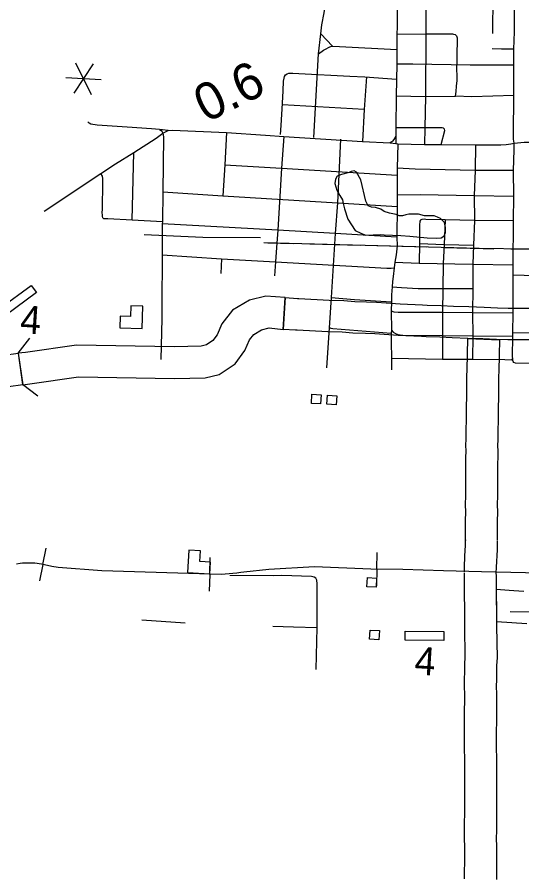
# Model space of a CAD drawing. Extents: x 1366406 to 1373462, y 376856 to 381998.
# Drawn here: x 1369209.2 to 1369273.7, y 379865.5 to 379974.8 of the extents above; entities that cross this region are included whole.
import ezdxf

# ---------------------------------------------------------------- set-up
doc = ezdxf.new("R2010")
doc.units = 0
for name, color, linetype in [('10', 7, 'Continuous'), ('15', 7, 'Continuous'), ('33', 7, 'Continuous'), ('34', 7, 'Continuous'), ('35', 7, 'Continuous'), ('37', 7, 'Continuous'), ('40', 7, 'Continuous'), ('43', 7, 'Continuous'), ('48', 7, 'Continuous'), ('56', 7, 'Continuous'), ('58', 7, 'Continuous')]:
    doc.layers.add(name, color=color, linetype=linetype)

msp = doc.modelspace()

# ---------------------------------------------------------------- linework, layer by layer
at = {"layer": '10'}
msp.add_line((1369266.5, 379908.05), (1369266.5, 379907.96), dxfattribs=at)
for points in [[(1369243.2, 379934.94), (1369243.45, 379938.99), (1369241.02, 379939.19), (1369238.93, 379938.67), (1369236.73, 379937.4), (1369235.4, 379935.65), (1369234.79, 379934.25), (1369234.25, 379933.5), (1369233.42, 379932.96), (1369232.72, 379932.79), (1369229.33, 379932.72), (1369216.84, 379932.9), (1369210.29, 379931.99), (1369209.39, 379931.88), (1369209.95, 379927.86)], [(1369243.2, 379934.94), (1369243.45, 379938.99), (1369245.03, 379938.89), (1369245.21, 379938.88), (1369249.1, 379938.68), (1369250.98, 379938.61), (1369252.35, 379938.5), (1369253.86, 379938.46), (1369255.11, 379938.4), (1369256.35, 379938.34), (1369258.16, 379938.21), (1369261.02, 379938.06), (1369261.59, 379938.05), (1369263.38, 379937.98), (1369264.95, 379937.91), (1369266.93, 379937.84), (1369268.87, 379937.76)], [(1369268.87, 379937.76), (1369270.58, 379937.7), (1369271.96, 379937.66), (1369274.8, 379937.64)], [(1369209.95, 379927.86), (1369210.85, 379927.98), (1369217.09, 379928.85), (1369229.34, 379928.67), (1369233.24, 379928.75), (1369235.06, 379929.19), (1369237.09, 379930.53), (1369238.33, 379932.23), (1369238.92, 379933.59), (1369239.46, 379934.3), (1369240.46, 379934.88), (1369241.42, 379935.12), (1369243.2, 379934.94)], [(1369268.71, 379933.72), (1369266.79, 379933.79), (1369264.79, 379933.86), (1369263.22, 379933.94), (1369261.47, 379934), (1369260.87, 379934.01), (1369257.91, 379934.17), (1369256.1, 379934.3), (1369254.92, 379934.36), (1369253.71, 379934.41), (1369252.12, 379934.46), (1369250.74, 379934.57), (1369248.93, 379934.63), (1369244.98, 379934.83), (1369244.78, 379934.84), (1369243.2, 379934.94)], [(1369266.5, 379907.96), (1369266.48, 379908.65), (1369266.49, 379909.32), (1369266.48, 379910), (1369266.51, 379910.73), (1369266.52, 379911.38), (1369266.51, 379912.78), (1369266.52, 379913.47), (1369266.52, 379914.19), (1369266.53, 379914.9), (1369266.52, 379915.65), (1369266.54, 379916.38), (1369266.53, 379917.14), (1369266.55, 379917.91), (1369266.56, 379918.56), (1369266.57, 379919.36), (1369266.55, 379920.12), (1369266.58, 379920.91), (1369266.61, 379924.57), (1369266.63, 379925.32), (1369266.65, 379926.04), (1369266.67, 379926.74), (1369266.66, 379928.95), (1369266.69, 379929.77), (1369266.75, 379931.75), (1369266.81, 379933.77), (1369270.85, 379933.62)], [(1369274.79, 379933.59), (1369271.89, 379933.61), (1369270.45, 379933.65), (1369268.71, 379933.72)], [(1369270.85, 379933.62), (1369270.8, 379931.63), (1369270.74, 379929.62), (1369270.71, 379928.88), (1369270.72, 379926.69), (1369270.7, 379925.93), (1369270.68, 379925.21), (1369270.66, 379924.5), (1369270.63, 379920.81), (1369270.6, 379920.09), (1369270.62, 379919.38), (1369270.61, 379918.5), (1369270.6, 379917.85), (1369270.58, 379917.11), (1369270.59, 379916.36), (1369270.57, 379915.62), (1369270.58, 379914.9), (1369270.57, 379914.16), (1369270.57, 379913.44), (1369270.56, 379912.77), (1369270.57, 379911.35), (1369270.56, 379910.62), (1369270.53, 379909.96), (1369270.54, 379909.33), (1369270.53, 379908.66), (1369270.55, 379908.05)], [(1369209.39, 379931.87), (1369198.35, 379930.34), (1369198.13, 379930.31)], [(1369209.39, 379931.88), (1369209.94, 379927.87)], [(1369209.95, 379927.86), (1369198.93, 379926.33), (1369198.71, 379926.3)], [(1369266.35, 379903.96), (1369266.38, 379904.71), (1369266.47, 379906.86), (1369266.48, 379907.16), (1369266.5, 379908.05)], [(1369270.55, 379907.96), (1369270.53, 379907.09), (1369270.52, 379906.75), (1369270.43, 379904.53), (1369270.39, 379903.76)], [(1369266.39, 379864.71), (1369266.39, 379865.72), (1369266.41, 379866.76), (1369266.4, 379867.81), (1369266.42, 379868.83), (1369266.38, 379869.82), (1369266.39, 379870.9), (1369266.39, 379871.94), (1369266.4, 379872.98), (1369266.41, 379874.02), (1369266.4, 379875.04), (1369266.4, 379876.08), (1369266.4, 379877.12), (1369266.4, 379878.16), (1369266.41, 379879.19), (1369266.4, 379880.19), (1369266.38, 379881.22), (1369266.37, 379882.14), (1369266.38, 379883.31), (1369266.39, 379885.08), (1369266.39, 379885.34), (1369266.39, 379886.35), (1369266.4, 379887.34), (1369266.4, 379888.31), (1369266.37, 379889.27), (1369266.39, 379890.25), (1369266.4, 379891.18), (1369266.42, 379892.15), (1369266.47, 379893.05), (1369266.42, 379896.96), (1369266.35, 379903.29), (1369266.35, 379903.83)], [(1369270.39, 379903.89), (1369270.4, 379903.34), (1369270.47, 379897.01), (1369270.52, 379892.97), (1369270.47, 379892), (1369270.45, 379891.13), (1369270.44, 379890.19), (1369270.42, 379889.28), (1369270.45, 379888.36), (1369270.45, 379887.33), (1369270.44, 379886.33), (1369270.44, 379885.32), (1369270.44, 379885.06), (1369270.43, 379883.29), (1369270.42, 379882.15), (1369270.43, 379881.27), (1369270.45, 379880.25), (1369270.46, 379879.19), (1369270.45, 379878.15), (1369270.45, 379877.12), (1369270.45, 379876.09), (1369270.45, 379875.05), (1369270.46, 379874), (1369270.45, 379872.96), (1369270.44, 379871.92), (1369270.44, 379870.88), (1369270.43, 379869.89), (1369270.47, 379868.87), (1369270.45, 379867.77), (1369270.46, 379866.74), (1369270.44, 379865.7), (1369270.44, 379864.65)], [(1369273.96, 379901.43), (1369273.31, 379901.48), (1369272.69, 379901.52), (1369272.08, 379901.56), (1369270.42, 379901.69), (1369270.47, 379897.6)], [(1369270.47, 379897.6), (1369272.42, 379897.48), (1369273.03, 379897.44), (1369273.68, 379897.39), (1369274.35, 379897.35)]]:
    msp.add_lwpolyline(points, dxfattribs=at)
at = {"layer": '15'}
msp.add_lwpolyline([(1369243.45, 379938.99), (1369243.2, 379934.94)], dxfattribs=at)
at = {"layer": '33'}
for points in [[(1369247.12, 379959.46), (1369247.73, 379970.16), (1369248.03, 379972.72), (1369248.16, 379973.86), (1369248.46, 379975.38), (1369248.71, 379977.22), (1369248.87, 379978.16), (1369249.08, 379980.55)], [(1369257.87, 379980.81), (1369257.76, 379976.94), (1369257.75, 379976.81), (1369257.76, 379973.6), (1369257.74, 379972.68), (1369257.74, 379970.7), (1369257.71, 379968.83), (1369257.65, 379964.78), (1369257.6, 379960.68), (1369257.6, 379959.64), (1369257.61, 379958.68)], [(1369261.45, 379979.35), (1369261.45, 379973.54), (1369261.41, 379972.71), (1369261.37, 379964.71), (1369261.32, 379960.7), (1369261.24, 379958.58)], [(1369269.97, 379972.76), (1369269.99, 379973.45), (1369270.01, 379976.84), (1369270.03, 379979.21)], [(1369257.06, 379931.24), (1369263.54, 379931.14), (1369267.4, 379931.12), (1369271.51, 379931.08), (1369272.36, 379931.06), (1369272.46, 379931.1), (1369272.53, 379931.2), (1369272.52, 379931.42), (1369272.56, 379934.05), (1369272.56, 379934.48), (1369272.58, 379937.07), (1369272.58, 379941.9), (1369272.59, 379943.2), (1369272.64, 379948.8), (1369272.69, 379951.96), (1369272.64, 379955.22), (1369272.71, 379957.87), (1369272.7, 379958.73), (1369272.64, 379959.23), (1369272.62, 379959.92), (1369272.67, 379964.74), (1369272.67, 379968.71), (1369272.66, 379970.76), (1369272.74, 379972.95), (1369272.76, 379973.47), (1369272.74, 379975.81)], [(1369248.03, 379972.72), (1369249.52, 379971.14), (1369249.52, 379971.14)], [(1369257.74, 379972.68), (1369261.41, 379972.71), (1369262.35, 379972.71), (1369264.82, 379972.7), (1369264.98, 379972.66), (1369265.18, 379972.6), (1369265.34, 379972.43), (1369265.45, 379972.19), (1369265.42, 379971.82), (1369265.37, 379970.16), (1369265.41, 379968.78)], [(1369247.73, 379970.16), (1369248.38, 379970.6), (1369248.69, 379970.79), (1369249, 379970.96), (1369249.16, 379971.04), (1369249.31, 379971.1), (1369249.52, 379971.14), (1369250.4, 379971.08), (1369257.74, 379970.7)], [(1369272.66, 379970.76), (1369271.58, 379970.74), (1369271.08, 379970.76), (1369269.9, 379970.79)], [(1369272.67, 379968.71), (1369269.96, 379968.72), (1369267.11, 379968.72), (1369259.79, 379968.82), (1369257.71, 379968.83)], [(1369258.45, 379968.85), (1369258.45, 379968.85)], [(1369265.23, 379964.76), (1369265.3, 379965.33), (1369265.36, 379966.01), (1369265.42, 379966.76), (1369265.41, 379968.78)], [(1369242.89, 379959.84), (1369242.97, 379960.97), (1369243.13, 379963.86), (1369243.21, 379965.43), (1369243.27, 379966.64), (1369243.34, 379967.02), (1369243.38, 379967.24), (1369243.52, 379967.45), (1369243.73, 379967.6), (1369243.92, 379967.68), (1369244.44, 379967.7), (1369245.22, 379967.65), (1369251.73, 379967.29), (1369253.65, 379967.2), (1369257.68, 379966.92)], [(1369253.84, 379967.19), (1369253.57, 379963.04), (1369253.36, 379958.96)], [(1369257.65, 379964.78), (1369261.37, 379964.71), (1369265.23, 379964.76)], [(1369272.67, 379964.81), (1369267.3, 379964.66), (1369265.23, 379964.76)], [(1369253.57, 379963.04), (1369243.12, 379963.65)], [(1369228.52, 379960.37), (1369227.41, 379960.5), (1369226.4, 379960.58), (1369223.31, 379960.78), (1369219.46, 379961.04), (1369218.67, 379961.16), (1369218.44, 379961.29), (1369218.27, 379961.44)], [(1369212.71, 379950.03), (1369219.92, 379954.84), (1369221.82, 379956.09), (1369224.13, 379957.56), (1369227, 379959.36), (1369227.86, 379960), (1369228.1, 379960.16), (1369228.52, 379960.37), (1369229.08, 379960.41), (1369235.99, 379960.09), (1369240.95, 379959.75), (1369243.29, 379959.59), (1369253.36, 379958.96), (1369256.88, 379958.77), (1369257.61, 379958.68), (1369257.85, 379958.64)], [(1369227.41, 379960.5), (1369227.63, 379960.34), (1369227.75, 379960.18), (1369227.86, 379960)], [(1369263.37, 379958.57), (1369263.85, 379960.36), (1369263.8, 379960.54), (1369263.67, 379960.64), (1369263.51, 379960.7), (1369261.32, 379960.7), (1369257.6, 379960.68)], [(1369227.86, 379960), (1369227.92, 379959.55), (1369227.85, 379952.5), (1369227.79, 379948.68), (1369227.78, 379948.44), (1369227.74, 379944.47), (1369227.71, 379937.9), (1369227.72, 379936.33), (1369227.58, 379931.1)], [(1369235.99, 379960.09), (1369235.76, 379955.98), (1369235.52, 379952.02)], [(1369243.29, 379959.59), (1369243, 379955.55), (1369242.53, 379947.62), (1369242.34, 379945.4), (1369242.24, 379943.55)], [(1369250.55, 379959.24), (1369250.13, 379951.11), (1369249.85, 379947.17), (1369249.35, 379938.99), (1369249.1, 379935.13), (1369248.73, 379930.02)], [(1369257.6, 379959.64), (1369257.49, 379959.42), (1369257.36, 379959.22), (1369257.18, 379959), (1369257.07, 379958.9), (1369256.88, 379958.77)], [(1369257.85, 379958.64), (1369257.76, 379955.52), (1369257.75, 379954.63), (1369257.77, 379952.15), (1369257.78, 379950.65), (1369257.73, 379946.7), (1369257.76, 379945.6), (1369257.64, 379944.46), (1369257.47, 379943.52), (1369257.37, 379942.79), (1369257.24, 379941.71), (1369257.19, 379941.06), (1369257.12, 379940.38), (1369257.05, 379939.34), (1369257.04, 379939.21), (1369257.05, 379938.47), (1369257.02, 379937.3), (1369257.04, 379934.84), (1369257.01, 379934.47), (1369257.02, 379933.31), (1369257.06, 379931.24), (1369257.05, 379929.75)], [(1369257.85, 379958.64), (1369261.24, 379958.58), (1369263.37, 379958.57), (1369267.79, 379958.5), (1369271.03, 379958.51), (1369271.71, 379958.55), (1369272.27, 379958.64), (1369272.7, 379958.73)], [(1369267.79, 379958.5), (1369267.72, 379955.26), (1369267.62, 379952.05), (1369267.63, 379948.87), (1369267.51, 379945.7), (1369267.45, 379943.29), (1369267.43, 379940.14), (1369267.41, 379937.08), (1369267.44, 379934.1), (1369267.4, 379931.12)], [(1369272.7, 379958.73), (1369273.15, 379958.76), (1369273.97, 379958.85), (1369274.62, 379958.86), (1369275.99, 379958.92), (1369277.82, 379958.93), (1369287.45, 379958.94)], [(1369223.95, 379948.88), (1369224.13, 379957.56)], [(1369235.76, 379955.98), (1369243, 379955.55), (1369257.75, 379954.63)], [(1369272.64, 379955.22), (1369267.72, 379955.26), (1369260.07, 379955.42), (1369257.76, 379955.52)], [(1369227.79, 379948.68), (1369223.95, 379948.88), (1369220.84, 379949.05), (1369220.33, 379949.08), (1369220.2, 379949.21), (1369220.15, 379949.34), (1369220.12, 379949.49), (1369220.11, 379949.93), (1369220.12, 379950.21), (1369220.18, 379953.78), (1369220.18, 379954.21), (1369220.13, 379954.53), (1369219.92, 379954.84)], [(1369227.85, 379952.5), (1369235.52, 379952.02), (1369250.13, 379951.11), (1369257.78, 379950.65)], [(1369257.77, 379952.15), (1369260.72, 379952.19), (1369267.62, 379952.05), (1369272.69, 379951.96)], [(1369257.73, 379946.7), (1369249.85, 379947.17), (1369242.53, 379947.62), (1369227.78, 379948.44)], [(1369272.64, 379948.8), (1369267.63, 379948.87), (1369263.9, 379948.94), (1369261.42, 379948.99), (1369261.22, 379949), (1369260.91, 379948.98), (1369260.81, 379948.95), (1369260.74, 379948.89), (1369260.67, 379948.77), (1369260.62, 379948.25), (1369260.61, 379945.9), (1369260.58, 379943.41)], [(1369263.9, 379948.94), (1369263.76, 379945.8), (1369263.63, 379943.37), (1369263.63, 379943.37), (1369263.62, 379940.18), (1369263.57, 379937.12), (1369263.54, 379934.16), (1369263.54, 379931.14)], [(1369260.61, 379945.9), (1369263.76, 379945.8), (1369267.51, 379945.7)], [(1369227.74, 379944.47), (1369235.34, 379943.93), (1369242.24, 379943.55), (1369256.46, 379942.75), (1369257, 379942.77), (1369257.37, 379942.79)], [(1369235.34, 379943.93), (1369235.24, 379942.09)], [(1369242.24, 379943.55), (1369242.11, 379941.76)], [(1369257.47, 379943.52), (1369260.58, 379943.41), (1369267.45, 379943.29), (1369272.59, 379943.2)], [(1369272.58, 379941.9), (1369275.39, 379941.82)], [(1369257.12, 379940.38), (1369258.31, 379940.28), (1369260.45, 379940.18), (1369262.42, 379940.18), (1369263.62, 379940.18), (1369265.51, 379940.14), (1369267.43, 379940.14)], [(1369249.35, 379938.99), (1369252.33, 379938.76), (1369257.05, 379938.47)], [(1369257.02, 379937.3), (1369257.36, 379937.19), (1369257.9, 379937.15), (1369263.57, 379937.12), (1369267.41, 379937.08), (1369272.58, 379937.07)], [(1369249.11, 379935.17), (1369249.29, 379935.1), (1369249.57, 379935.05), (1369257.01, 379934.47)], [(1369257.04, 379934.84), (1369257.25, 379934.6), (1369257.56, 379934.39), (1369257.85, 379934.27), (1369258.48, 379934.21), (1369263.54, 379934.16), (1369267.44, 379934.1), (1369272.56, 379934.05)], [(1369287.35, 379934.58), (1369281.27, 379934.48), (1369280.6, 379934.45), (1369279.34, 379934.45), (1369279.14, 379934.45), (1369276.63, 379934.45), (1369272.56, 379934.48)], [(1369276.72, 379930.57), (1369272.89, 379930.62), (1369272.69, 379930.7), (1369272.57, 379930.82), (1369272.53, 379930.96), (1369272.53, 379931.2)], [(1369272.21, 379898.87), (1369287.08, 379898.65), (1369293.15, 379898.58), (1369295.08, 379898.56), (1369301.85, 379898.47)]]:
    msp.add_lwpolyline(points, dxfattribs=at)
at = {"layer": '34'}
for points in [[(1369225.46, 379947.07), (1369232.97, 379946.72), (1369240.32, 379946.69)], [(1369247.41, 379891.48), (1369247.54, 379896.82), (1369247.57, 379901.78), (1369247.57, 379902.43), (1369247.53, 379902.88), (1369247.37, 379903.14), (1369247.19, 379903.25), (1369246.81, 379903.35), (1369243.06, 379903.49), (1369241.99, 379903.45), (1369236.4, 379903.5)], [(1369230.69, 379897.37), (1369225.18, 379897.77)], [(1369241.91, 379897.01), (1369244.53, 379896.91), (1369247.54, 379896.82)]]:
    msp.add_lwpolyline(points, dxfattribs=at)
at = {"layer": '35'}
for points in [[(1369251.91, 379955.11), (1369251.65, 379955), (1369250.68, 379954.74), (1369250.11, 379954.5), (1369249.91, 379954.14), (1369249.81, 379953.57), (1369250.08, 379952.74), (1369250.18, 379952.52), (1369250.47, 379952.03), (1369250.78, 379951.49), (1369250.88, 379951.03), (1369251.05, 379950.36), (1369251.48, 379949.04), (1369251.93, 379948.29), (1369252.4, 379947.59), (1369253.11, 379947.22), (1369253.78, 379946.99), (1369255.59, 379947.05), (1369256.1, 379947.02)], [(1369256.1, 379947.02), (1369258.24, 379946.92), (1369259.38, 379946.83), (1369261.61, 379946.65), (1369262.77, 379946.59), (1369263.39, 379946.63), (1369263.72, 379946.84), (1369263.94, 379947.27), (1369263.96, 379947.94), (1369263.8, 379948.6), (1369263.3, 379949.1), (1369262.92, 379949.28), (1369262.49, 379949.43), (1369261.28, 379949.44), (1369260.5, 379949.68), (1369259.96, 379949.67), (1369259.27, 379949.67), (1369258.86, 379949.57), (1369258.46, 379949.44), (1369258.04, 379949.45), (1369257.64, 379949.62), (1369256.79, 379949.78), (1369256.11, 379949.98), (1369255.68, 379950.31), (1369254.99, 379950.52), (1369254.5, 379950.57), (1369254.08, 379950.73), (1369253.79, 379951.32), (1369253.11, 379954.03), (1369252.57, 379955.01), (1369252.3, 379955.2), (1369251.91, 379955.11)]]:
    msp.add_lwpolyline(points, dxfattribs=at)
at = {"layer": '37'}
for points in [[(1369209.39, 379931.88), (1369210.86, 379933.82)], [(1369211.88, 379926.4), (1369209.94, 379927.87)]]:
    msp.add_lwpolyline(points, dxfattribs=at)
at = {"layer": '40'}
for p, q in [((1369212.51, 379904.88), (1369212.94, 379906.97)), ((1369233.83, 379903.63), (1369233.9, 379905.77)), ((1369255.16, 379904.29), (1369255.2, 379906.43)), ((1369212.51, 379904.88), (1369212.08, 379902.78)), ((1369233.83, 379903.63), (1369233.77, 379901.5)), ((1369255.16, 379904.29), (1369255.13, 379902.15))]:
    msp.add_line(p, q, dxfattribs=at)
msp.add_lwpolyline([(1369350.18, 379901.69), (1369311.51, 379902.74), (1369293.42, 379903.21), (1369277.92, 379903.72), (1369268.52, 379903.93), (1369263.7, 379904.07), (1369258.5, 379904.23), (1369254.42, 379904.3), (1369247.2, 379904.6), (1369241.4, 379904.25), (1369238.18, 379903.9), (1369237.81, 379903.86), (1369237.29, 379903.77), (1369235.28, 379903.59), (1369220.06, 379904.06), (1369214.47, 379904.51), (1369213.67, 379904.64), (1369212.34, 379904.91), (1369211.48, 379905.04), (1369210.58, 379905.07), (1369210.16, 379905.04), (1369209.93, 379905.05), (1369209.63, 379905.01), (1369209.17, 379904.93)], dxfattribs=at)
at = {"layer": '43'}
for points in [[(1369240.75, 379946.04), (1369268.24, 379945.31), (1369274.5, 379945.21), (1369278.25, 379945.43), (1369284.48, 379946), (1369287.13, 379946.46), (1369299.97, 379948.83), (1369306.31, 379949.86), (1369307.96, 379950.28), (1369308.5, 379950.58), (1369309.76, 379951.17), (1369313.65, 379953.1), (1369317.24, 379954.99), (1369323.94, 379958.01), (1369325.5, 379958.87), (1369326.69, 379959.63), (1369327.27, 379960.12), (1369327.85, 379960.68), (1369328.49, 379961.35), (1369329.68, 379961.38), (1369330.39, 379962.24), (1369335.86, 379970.19)], [(1369241.27, 379946.01), (1369244.48, 379945.92)], [(1369246.61, 379945.87), (1369253.03, 379945.69)], [(1369255.16, 379945.64), (1369261.58, 379945.47)], [(1369263.71, 379945.41), (1369268.76, 379945.28), (1369270.13, 379945.25)], [(1369272.27, 379945.22), (1369275.02, 379945.18), (1369278.25, 379945.37)]]:
    msp.add_lwpolyline(points, dxfattribs=at)
at = {"layer": '48'}
for p, q in [((1369218.95, 379968.86), (1369216.46, 379965.11)), ((1369216.7, 379969), (1369218.71, 379964.97)), ((1369215.46, 379967.13), (1369219.95, 379966.85))]:
    msp.add_line(p, q, dxfattribs=at)
at = {"layer": '56'}
for points in [[(1369207.75, 379936.72), (1369207.08, 379937.63), (1369211.05, 379940.54), (1369211.72, 379939.63)], [(1369246.81, 379925.48), (1369246.88, 379926.65), (1369248.05, 379926.58), (1369247.98, 379925.41)], [(1369248.8, 379925.37), (1369248.87, 379926.54), (1369250.05, 379926.46), (1369249.97, 379925.29)], [(1369253.9, 379902.05), (1369253.98, 379903.21), (1369255.15, 379903.14), (1369255.08, 379901.97)], [(1369254.25, 379895.34), (1369254.33, 379896.51), (1369255.5, 379896.44), (1369255.43, 379895.27)], [(1369258.8, 379895.23), (1369258.81, 379896.36), (1369263.74, 379896.31), (1369263.72, 379895.19)]]:
    msp.add_lwpolyline(points, close=True, dxfattribs=at)
at = {"layer": '58'}
for points in [[(1369225.19, 379935.03), (1369225.28, 379937.89), (1369223.78, 379937.94), (1369223.73, 379936.59), (1369222.38, 379936.63), (1369222.34, 379935.12)], [(1369230.99, 379903.87), (1369233.84, 379903.69), (1369233.94, 379905.2), (1369232.59, 379905.28), (1369232.67, 379906.63), (1369231.17, 379906.72)]]:
    msp.add_lwpolyline(points, close=True, dxfattribs=at)

# ---------------------------------------------------------------- texts
at = {"layer": '48'}
msp.add_text('0.6', height=4.752, rotation=26.3383, dxfattribs=at).set_placement((1369233.35, 379961.29))
at = {"layer": '56'}
for p in [(1369209.55, 379934.47), (1369259.91, 379890.85)]:
    msp.add_text('4', height=3.56, rotation=356.4139, dxfattribs=at).set_placement(p)

doc.saveas('drawing.dxf')
